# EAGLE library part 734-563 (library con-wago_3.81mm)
Serie 734, Federleiste mit abgewinkelten Einlötstiften / Series 734, Female connector with angled solder pins Polzahl / Pole No.: 3 Bemessungsspannung / Rated Voltage: 160 V Nennstrom / Nominal Current: 10 A Lötstiftlänge: / Solder Pin Length: 3.8 mm Farbe / Color: orange / orange Stand: 01.01.2012. Die jeweils aktuellen Daten zu diesem Artikel finden Sie in unserem Produktkatalog, den Sie unter www.wago.com einsehen können. As of: 01/01/2012. Please find the newest data for this article in our product catalogue, which can be viewed under www.wago.com.
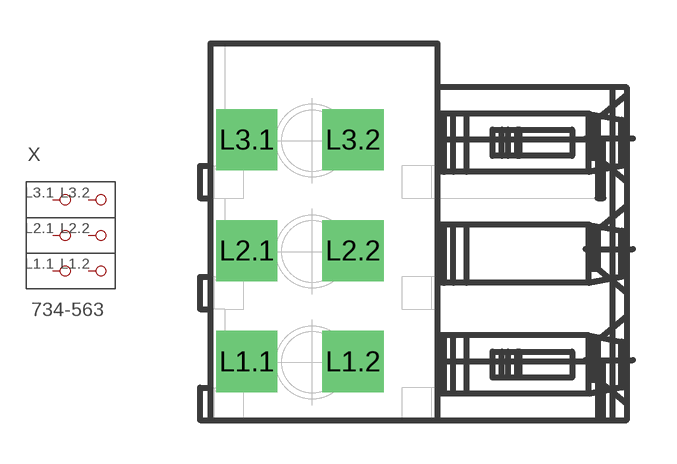
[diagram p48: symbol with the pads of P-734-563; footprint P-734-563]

Designator prefix X

## 734-563  [P-734-563]
L1.1  P1.1
L1.2  P1.2
L2.1  P2.1
L2.2  P2.2
L3.1  P3.1
L3.2  P3.2

## Footprint P-734-563 (pad centres in mm)
drill 1.4 square: L1.1 -5.832,-4.455; L1.2 -2.182,-4.455; L2.1 -5.832,-0.645; L2.2 -2.182,-0.645; L3.1 -5.832,3.165; L3.2 -2.182,3.165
